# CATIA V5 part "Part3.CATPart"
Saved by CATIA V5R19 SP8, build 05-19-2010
Part number: Part3
Bounding box of the stored display mesh (mm): x 0 to 632, y 0 to 592, z 0 to 190
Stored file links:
  G:\EU_thinkMotion\CFAO_2010\SIL_groupe2\SIL_groupe2\A reprendre\fnongaibaa\fnongaibaa\Part3.CATPart
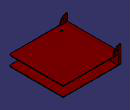
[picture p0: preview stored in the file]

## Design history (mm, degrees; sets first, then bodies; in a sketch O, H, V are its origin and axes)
Body1 (main body)
  Sketch1 on xy-plane, origin (0, 0, 0), H (1, 0, 0), V (0, 1, 0)
    line L1 (0, 592) -> (632, 592)
    line L2 (632, 592) -> (632, 0)
    line L3 (632, 0) -> (0, 0)
    line L4 (0, 0) -> (0, 592)
    point P3 (632, 0)
    length L3 = 632
    length L2 = 592
    horizontal: L1 H, L3 H
    vertical: L2 V, L4 V
    coincidence: P3 H
  Pad1: profile Sketch1, direction (0, 0, 1), length 110
  Fillet1: radius 20, on edge [face of Pad1 from Sketch1.L2 | face of Pad1 from Sketch1.L3]
  Sketch2 on face of Pad1 from Sketch1.L2, origin (632, 0, 0), H (0, 1, 0), V (0, 0, 1)
    line L1 (-40, 105) -> (650, 105)
    line L2 (-40, 5) -> (650, 5)
    reference projected line E1 (0, 0) -> (632, 0) from edge [start face of Pad1 | face of Pad1 from Sketch1.L2]
    reference projected line E2 (0, 110) -> (632, 110) from edge [face of Pad1 from Sketch1.L2 | end face of Pad1]
    line L3 (-40, 5) -> (-40, 105)
    line L4 (650, 5) -> (650, 105)
    distance L2 E1 = 5
    distance L1 E2 = 5
    horizontal: L1 H, L2 H
    vertical: L3 V, L4 V
  Pocket1: profile Sketch2, direction (-1, 0, 0), length 200
  Sketch3 on end face of Pad1, origin (415.2374, 227.835, 110), H (1, 0, 0), V (0, 1, 0)
    point P1 (-295.2374, -162.835)
    reference projected line E1 (-415.2374, 404.165) -> (-415.2374, -227.835) from edge [face of Pad1 | end face of Pad1]
    reference projected line E2 (-415.2374, -227.835) -> (216.7626, -227.835) from edge [face of Pad1 | end face of Pad1]
    distance P1 E1 = 120
    distance P1 E2 = 65
  Hole1: placed by Sketch3, at (120, 65, 110) direction (0, 0, -1), diameter 20, through (limit type 3)
  Sketch4 on end face of Pocket1, origin (432, 0, 0), H (0, 1, 0), V (0, 0, 1)
    line L1 (5, 105) -> (592, 105)
    line L2 (592, 105) -> (592, 5)
    line L3 (592, 5) -> (5, 5)
    line L4 (5, 5) -> (5, 105)
    reference projected line E1 (650, 105) -> (-40, 105) from edge [end face of Pocket1 | face of Pocket1 from Sketch2.L1]
    reference projected line E2 (-40, 5) -> (650, 5) from edge [end face of Pocket1 | face of Pocket1 from Sketch2.L2]
    reference projected line E3 (592, 105) -> (592, 5) from edge [end face of Pocket1 | face of Pad1 from Sketch1.L1]
    reference projected line E4 (0, 105) -> (0, 5) from edge [face of Pad1 from Sketch1.L3 | end face of Pocket1]
    distance L4 E4 = 5
    horizontal: L1 H, L3 H
    vertical: L2 V, L4 V
    coincidence: L1 E1, L3 E2, L2 E3
  Pocket2: profile Sketch4, direction (-1, 0, 0), length 400
  Sketch5 on end face of Pad1, origin (0, 0, 110), H (1, 0, 0), V (0, 1, 0)
    line L1 (0, 592) -> (80, 592)
    line L2 (80, 592) -> (80, 582)
    line L3 (80, 582) -> (0, 582)
    line L4 (0, 582) -> (0, 592)
    reference projected line E1 (632, 592) -> (0, 592) from edge [face of Pad1 from Sketch1.L1 | end face of Pad1]
    reference projected line E2 (0, 632) -> (0, 0) from edge [face of Pad1 from Sketch1.L4 | end face of Pad1]
    length L3 = 80
    length L4 = 10
    horizontal: L1 H, L3 H
    vertical: L2 V, L4 V
    coincidence: L1 E1, L4 E2
  Shaft1: profile Sketch5, axis Sketch5.L4, angle 90
  Sketch6 on end face of Pad1, origin (0, 0, 110), H (1, 0, 0), V (0, 1, 0)
    line L1 (0, 10) -> (80, 10)
    line L2 (80, 10) -> (80, 0)
    line L3 (80, 0) -> (0, 0)
    line L4 (0, 0) -> (0, 10)
    reference projected line E1 (0, 632) -> (0, 0) from edge [face of Shaft1 | end face of Pad1]
    reference projected line E2 (0, 0) -> (632, 0) from edge [face of Pad1 from Sketch1.L3 | end face of Pad1]
    length L3 = 80
    length L4 = 10
    horizontal: L1 H, L3 H
    vertical: L2 V, L4 V
    coincidence: L4 E1, L3 E2
  Shaft2: profile Sketch6, axis Sketch6.L4, angle 90
  Sketch7 on face of Shaft1, origin (16.6126, 592, 150.2549), H (1, 0, 0), V (0, 0, -1)
    point P1 (18.3874, 5.2549)
    reference projected line E1 (615.3874, 40.2549) -> (-16.6126, 40.2549) from edge [face of Shaft1 | end face of Pad1]
    reference projected line E2 (-16.6126, 150.2549) -> (-16.6126, 40.2549) from edge [face of Shaft2 | face of Shaft1]
    distance P1 E1 = 35
    distance P1 E2 = 35
  Hole2: placed by Sketch7, at (35, 592, 145) direction (0, -1, 0), diameter 20, through (limit type 3)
